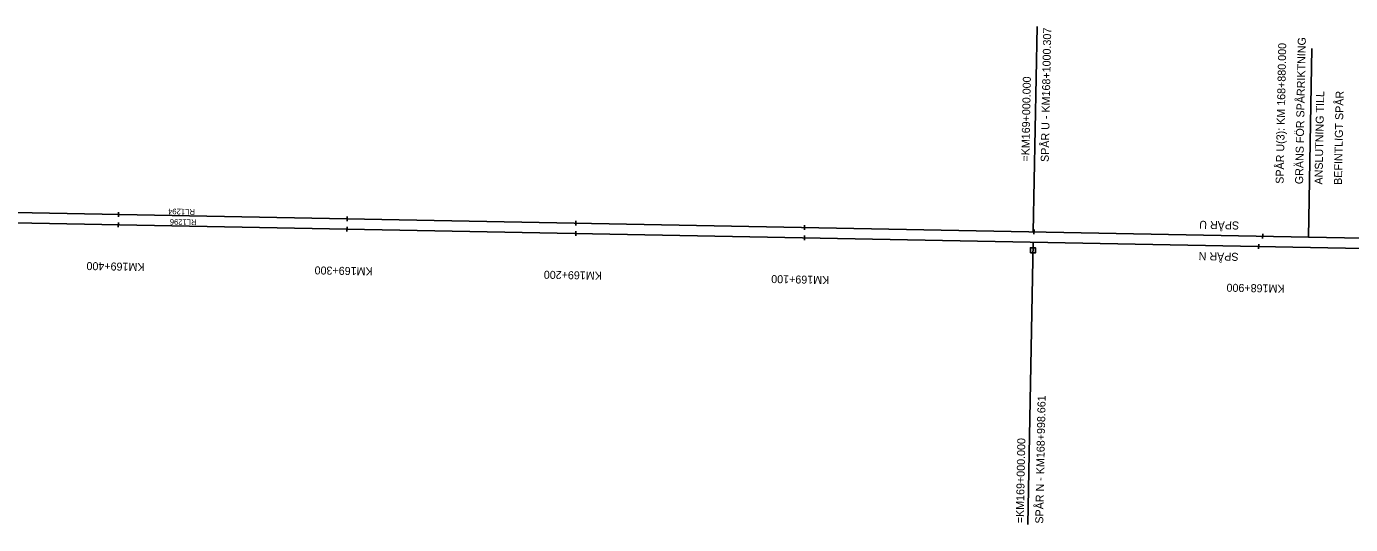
# Model space of a CAD drawing. Extents: x 185262 to 188870, y 6548921 to 6550022.
# Drawn here: x 185841 to 186420, y 6549786 to 6550004 of the extents above; entities that cross this region are included whole.
import ezdxf

# ---------------------------------------------------------------- set-up
doc = ezdxf.new("R2010")
doc.units = 0
for name, color, linetype in [('Befintligt spår som justeras', 7, 'Continuous'), ('Gräns för anslutning L', 7, 'Continuous'), ('Gräns för anslutning T', 7, 'Continuous'), ('Kilometertavla P', 7, 'Continuous'), ('Konnektion längdmätning L', 7, 'Continuous'), ('Konnektion längdmätning T', 7, 'Continuous'), ('Längdm markering (primär) L', 7, 'Continuous'), ('Längdmätning T', 7, 'Continuous'), ('Spår bef projekterat behålls L', 7, 'Continuous'), ('Spår nr T', 7, 'Continuous'), ('Spårgeometri T', 7, 'Continuous')]:
    doc.layers.add(name, color=color, linetype=linetype)

msp = doc.modelspace()

# ---------------------------------------------------------------- linework, layer by layer
at = {"layer": 'Befintligt spår som justeras'}
msp.add_line((186556.53, 6549908.61), (186401.75, 6549911.55), dxfattribs=at)
at = {"layer": 'Gräns för anslutning L'}
msp.add_line((186401.75, 6549911.55), (186403.32, 6549993.96), dxfattribs=at)
at = {"layer": 'Kilometertavla P'}
msp.add_lwpolyline([(186280.19, 6549904.6), (186282.44, 6549904.6), (186282.44, 6549906.85), (186280.19, 6549906.85)], close=True, dxfattribs=at)
at = {"layer": 'Konnektion längdmätning L'}
for points in [[(186281.47, 6549913.83), (186283.17, 6550003.54)], [(186281.38, 6549909.3), (186279.04, 6549785.98)]]:
    msp.add_lwpolyline(points, dxfattribs=at)
at = {"layer": 'Längdm markering (primär) L'}
for points in [[(185881.43, 6549915.89), (185881.47, 6549917.89)], [(185881.52, 6549920.41), (185881.56, 6549922.41)], [(185981.5, 6549918.52), (185981.54, 6549920.52)], [(186081.48, 6549916.62), (186081.52, 6549918.62)], [(185981.42, 6549913.99), (185981.45, 6549915.99)], [(186081.4, 6549912.1), (186081.44, 6549914.1)], [(186181.38, 6549910.2), (186181.42, 6549912.2)], [(186181.47, 6549914.72), (186181.5, 6549916.72)], [(186281.75, 6549912.82), (186281.79, 6549914.82)], [(186381.74, 6549910.92), (186381.77, 6549912.92)], [(186380.01, 6549906.43), (186380.04, 6549908.43)]]:
    msp.add_lwpolyline(points, dxfattribs=at)
at = {"layer": 'Spår bef projekterat behålls L'}
for p, q in [((186401.75, 6549911.55), (185262.5, 6549933.16)), ((186440.01, 6549906.29), (185262.41, 6549928.63))]:
    msp.add_line(p, q, dxfattribs=at)

# ---------------------------------------------------------------- texts
at = {"layer": 'Gräns för anslutning T'}
for s, p in [('GRÄNS FÖR SPÅRRIKTNING', (186399.41, 6549934.63)), ('SPÅR U(3): KM 168+880.000', (186390.91, 6549934.8)), ('ANSLUTNING TILL ', (186407.91, 6549934.47)), ('BEFINTLIGT SPÅR', (186416.41, 6549934.31))]:
    msp.add_text(s, height=3.5, rotation=88.91329, dxfattribs=at).set_placement(p)
at = {"layer": 'Konnektion längdmätning T'}
for s, p in [('SPÅR U - KM168+1000.307', (186288.22, 6549944.33)), ('=KM169+000.000 ', (186279.72, 6549944.49)), ('SPÅR N - KM168+998.661', (186285.81, 6549786.34)), ('=KM169+000.000', (186277.31, 6549786.5))]:
    msp.add_text(s, height=3.5, rotation=88.91329, dxfattribs=at).set_placement(p)
at = {"layer": 'Längdmätning T'}
for s, p in [('KM169+400', (185892.93, 6549900.17)), ('KM169+300', (185992.67, 6549898.28)), ('KM169+200', (186092.87, 6549896.38)), ('KM169+100', (186192.31, 6549894.49)), ('KM168+900', (186391.37, 6549890.71))]:
    msp.add_text(s, height=3.5, rotation=178.91329, dxfattribs=at).set_placement(p)
at = {"layer": 'Spår nr T'}
for s, p in [('SPÅR U', (186371.5, 6549918.33)), ('SPÅR N', (186371.24, 6549904.64))]:
    msp.add_text(s, height=3.5, rotation=178.91329, dxfattribs=at).set_placement(p)
at = {"layer": 'Spårgeometri T'}
for s, p in [('RL1294', (185914.95, 6549923.78)), ('RL1296', (185915.69, 6549919.24))]:
    msp.add_text(s, height=2.5, rotation=178.91329, dxfattribs=at).set_placement(p)

doc.saveas('drawing.dxf')
